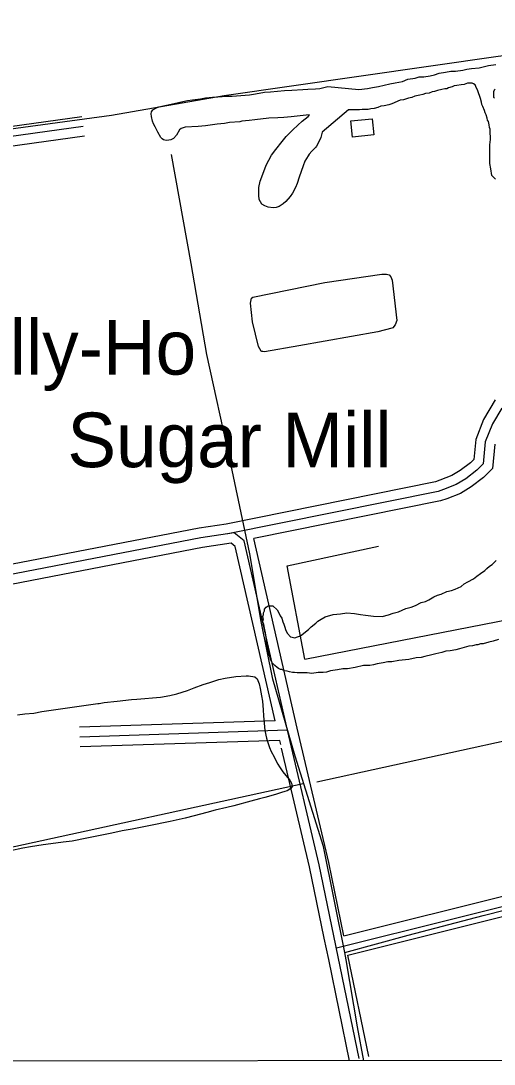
# Model space of a CAD drawing. Extents: x 3324104 to 3361979, y 612876 to 638273.
# Drawn here: x 3330722 to 3331443, y 618257 to 619844 of the extents above; entities that cross this region are included whole.
import ezdxf

# ---------------------------------------------------------------- set-up
doc = ezdxf.new("R2010")
doc.units = 0
for name, color, linetype in [('V-BLDG-IDEN', 7, 'Continuous'), ('V-BLDG-OTLN', 7, 'Continuous'), ('V-DTCH-CNTR', 7, 'Continuous'), ('V-GRID-FRAM', 7, 'Continuous'), ('V-ROAD-CNTR', 7, 'Continuous'), ('V-SITE-VEGE', 7, 'Continuous'), ('V-TOPO-SHOR', 7, 'Continuous')]:
    doc.layers.add(name, color=color, linetype=linetype)

msp = doc.modelspace()

# ---------------------------------------------------------------- linework, layer by layer
at = {"layer": 'V-BLDG-OTLN'}
msp.add_lwpolyline([(3331224.6, 619691.7), (3331257, 619695.1), (3331259.6, 619670.5), (3331227.2, 619667.1)], close=True, dxfattribs=at)
at = {"layer": 'V-DTCH-CNTR'}
for points in [[(3331244.5, 618262.2), (3331234.4, 618313.6), (3331217.5, 618415.7), (3331215.2, 618426.9), (3331182.8, 618587.9), (3331139.8, 618725.2), (3331105.6, 618842.5), (3331087.8, 618930.2), (3331070.9, 619033.1), (3331063.4, 619069.4), (3331040.2, 619177.1), (3331005.4, 619336.6), (3330981.6, 619474.6), (3330951.6, 619640.5)], [(3331215.2, 618426.9), (3331311.8, 618453.3), (3331425.9, 618482.8), (3331525.6, 618508.5), (3331632.5, 618535.7), (3331741.9, 618566), (3331832, 618591.7), (3331966.9, 618626.7), (3332061.8, 618649.2)]]:
    msp.add_lwpolyline(points, dxfattribs=at)
at = {"layer": 'V-GRID-FRAM'}
msp.add_lwpolyline([(3328194.1, 636440.7), (3359767.9, 636495.9), (3359807.6, 618312.1), (3328217.9, 618256.9), (3328194.1, 636440.7)], dxfattribs=at)
at = {"layer": 'V-ROAD-CNTR'}
for points in [[(3330007.1, 619586.3), (3330815, 619698.5)], [(3329995.1, 619569.5), (3330817.1, 619683.7)], [(3330012.9, 619556.8), (3330819.2, 619668.8)], [(3331444.2, 619267.6), (3331426.5, 619237.3), (3331414.5, 619206.9), (3331411.5, 619176.8), (3331406.4, 619171.7), (3331390.9, 619159.9), (3331378.2, 619152.2), (3331360.1, 619145), (3331353.2, 619142.6), (3331034.6, 619078.4)], [(3331454.2, 619254.8), (3331440, 619230.7), (3331429.2, 619203.4), (3331425.9, 619170), (3331416.3, 619160.4), (3331399.4, 619147.5), (3331384.9, 619138.7), (3331365.3, 619131), (3331357.2, 619128.1), (3331037.1, 619063.6)], [(3331443.9, 619199.8), (3331440.2, 619163.2), (3331426.2, 619149.1), (3331407.8, 619135.1), (3331391.6, 619125.2), (3331370.5, 619116.9), (3331361.2, 619113.6), (3331076.7, 619056.3)], [(3331034.6, 619078.4), (3330993.6, 619072.4), (3330135.7, 618906.7)], [(3331128.1, 618764.7), (3331062, 619053), (3331046.8, 619065), (3330996.1, 619057.6), (3330076.2, 618879.9), (3328787.7, 618630.3), (3328741.5, 618619.1), (3328711.6, 618607), (3328637.2, 618572.5)], [(3331109.4, 618779.1), (3331048.6, 619044.5), (3331042.6, 619049.2), (3330998.6, 619042.8), (3330140.4, 618877)], [(3331142.7, 618768), (3331076.7, 619056.3)], [(3331109.4, 618779.1), (3330811.3, 618769.4)], [(3331128.1, 618764.7), (3330811.8, 618754.5)], [(3331237.4, 618265.3), (3331176.3, 618560.3), (3331128.1, 618764.7)], [(3331214, 618452), (3331191, 618563.5), (3331142.7, 618768.1)], [(3331116.3, 618749.3), (3330812.3, 618739.5)], [(3331117.8, 618743.1), (3331116.3, 618749.3)], [(3331184.1, 618448.5), (3331161.7, 618557), (3331119, 618737.8)], [(3331202.5, 618433.7), (3331739.9, 618567.9), (3331755.7, 618571.8), (3331766.8, 618579.1), (3331772.9, 618588.7), (3331773.1, 618599.3), (3331778, 618664.4)], [(3331214, 618452), (3331736.2, 618582.4), (3331743.4, 618584.2)], [(3331220.1, 618422.6), (3331743.5, 618553.3), (3331753.8, 618555.9)], [(3331190.8, 618416.2), (3331184.1, 618448.5)], [(3331222.7, 618262.2), (3331190.8, 618416.2)], [(3331252.1, 618268.3), (3331220.1, 618422.6)]]:
    msp.add_lwpolyline(points, dxfattribs=at)
at = {"layer": 'V-SITE-VEGE'}
for points in [[(3331055.5, 619690.5), (3331039.7, 619689.1), (3331032.3, 619688), (3331021.3, 619686.7), (3331013.9, 619685.6), (3331003.4, 619684.3), (3330991.9, 619683.4), (3330972.1, 619682.1), (3330966.4, 619680.2), (3330963.5, 619678.3), (3330959.2, 619670), (3330954.7, 619665.2), (3330950.4, 619663.1), (3330944.2, 619662.1), (3330941.5, 619662.5), (3330939.3, 619663.1), (3330937.2, 619664.5), (3330935.5, 619666.6), (3330930.9, 619674.8), (3330928.4, 619679.5), (3330926.8, 619682.6), (3330924.2, 619687.3), (3330922.4, 619691.2), (3330920.9, 619698.6), (3330920.6, 619702.7), (3330921.2, 619705.4), (3330923.1, 619708.5), (3330927.8, 619711.2), (3330932.5, 619712.9), (3330944.1, 619715.7), (3330955.8, 619718.2), (3330964.4, 619720.3), (3330976, 619722.9), (3330983.6, 619724), (3330995.7, 619725.5), (3331003.3, 619726.6), (3331014.1, 619727.9), (3331022.1, 619728.4), (3331035.3, 619729.1), (3331043.9, 619729.5), (3331070.3, 619731.6), (3331079.2, 619732.9), (3331093, 619735.2), (3331102.2, 619735.9), (3331123.6, 619737.9), (3331134.6, 619738.4), (3331151.3, 619739.6), (3331159.3, 619740), (3331170.8, 619740.3), (3331177.4, 619740.8), (3331189.4, 619743.9), (3331236.9, 619739.6), (3331249.7, 619741.1), (3331257.7, 619742.7), (3331266.4, 619744.2), (3331284, 619748.1), (3331292, 619749.6), (3331303.1, 619751.9), (3331311.1, 619755.1), (3331322.3, 619756.6), (3331328.7, 619758.9), (3331335.8, 619758.9), (3331345.4, 619760.4), (3331351.8, 619762), (3331359, 619764.3), (3331368.5, 619765.8), (3331376.5, 619767.4), (3331383.7, 619767.3), (3331394.8, 619768.9), (3331401.2, 619770.4), (3331408.4, 619771.2), (3331419.6, 619772.7), (3331425.9, 619774.2), (3331433.9, 619775.8), (3331445.1, 619777.3)], [(3331436.5, 619679.4), (3331435.7, 619681.8), (3331434.9, 619685.8), (3331434.2, 619690.6), (3331432.6, 619693), (3331431.8, 619696.1), (3331430.3, 619700.9), (3331428.7, 619704.1), (3331427.9, 619707.3), (3331425.6, 619713.7), (3331424, 619716.9), (3331423.2, 619720.1), (3331421.6, 619725.7), (3331417.7, 619737.7), (3331414.6, 619744), (3331413.8, 619746.4), (3331411.4, 619748), (3331409.1, 619748.9), (3331401.9, 619748.9), (3331397.1, 619747.3), (3331392.3, 619746.6), (3331385.9, 619745.8), (3331381.9, 619745.1), (3331378.8, 619743.5), (3331373.2, 619741.9), (3331370.8, 619740.3), (3331367.6, 619740.4), (3331362.8, 619739.6), (3331356.4, 619738), (3331351.6, 619736.5), (3331348.4, 619735.7), (3331343.6, 619734.1), (3331338.1, 619733.4), (3331334.1, 619731.8), (3331329.3, 619731.1), (3331322.1, 619729.5), (3331317.3, 619727.1), (3331312.5, 619726.4), (3331304.5, 619724), (3331299.8, 619723.3), (3331287, 619717.8), (3331282.2, 619716.2), (3331275, 619714.7), (3331270.2, 619713.9), (3331265.4, 619712.3), (3331259.9, 619710.8), (3331255.1, 619710), (3331251.1, 619709.3), (3331241.5, 619709.3), (3331237.5, 619708.5), (3331220.8, 619708.7), (3331180.8, 619674.6), (3331180, 619670.5), (3331178.6, 619666.6), (3331174.7, 619657.7), (3331172.1, 619653.3), (3331170.8, 619651.3), (3331167.8, 619648.1), (3331165.3, 619645.7), (3331161.2, 619641.1), (3331159.4, 619638.8), (3331154.7, 619630.3), (3331151.9, 619623.5), (3331146, 619605.9), (3331143, 619596.4), (3331140.5, 619590.4), (3331135.9, 619581.8), (3331132.2, 619576.6), (3331125.8, 619569.3), (3331121.7, 619565.4), (3331115.6, 619561.6), (3331111.1, 619560.1), (3331106.5, 619559.7), (3331098.7, 619560.7), (3331093.7, 619562.3), (3331089, 619565), (3331085.2, 619572.3), (3331084.3, 619578.7), (3331084.7, 619590.3), (3331086.7, 619600), (3331092.1, 619614.8), (3331095.8, 619624.4), (3331103.9, 619639.5), (3331110.5, 619648.2), (3331119.8, 619660.6), (3331126.2, 619668.1), (3331136.2, 619678.2), (3331143.8, 619685.3), (3331150.6, 619691.1), (3331159.8, 619698.4), (3331161.6, 619701.1), (3331156.5, 619700.6), (3331147.2, 619699.3), (3331133.8, 619698), (3331122.5, 619697.1), (3331113.4, 619696.6), (3331099.6, 619696.1), (3331078.6, 619693.1), (3331069.7, 619692.4), (3331058.8, 619691.1), (3331055.5, 619690.5)], [(3331444, 619739.9), (3331442.4, 619738.3), (3331441.6, 619735.9), (3331441.6, 619727.9), (3331443.2, 619726.3)], [(3331444.8, 619602.9), (3331439.2, 619608.5), (3331437.7, 619618.8), (3331436.1, 619626.8), (3331436.3, 619655.5), (3331437.2, 619663.4), (3331437.2, 619667.4), (3331436.4, 619673), (3331436.5, 619679.4)], [(3331095.4, 618906.6), (3331094.6, 618912.9), (3331093.1, 618920.1), (3331092.3, 618925.7), (3331090.7, 618929.7), (3331091.6, 618933.7), (3331090.8, 618937.7), (3331091.6, 618940.8), (3331091.6, 618943.2), (3331093.2, 618946.4), (3331093.2, 618948.8), (3331095.7, 618952), (3331098.9, 618954.3), (3331106, 618954.3), (3331112.4, 618947.9), (3331115.5, 618942.3), (3331117.1, 618939.1), (3331119.4, 618935.1), (3331121, 618929.5), (3331122.6, 618926.3), (3331123.3, 618923.1), (3331125.7, 618916.7), (3331128.1, 618911.9), (3331132.8, 618907.1), (3331135.2, 618906.3), (3331139.2, 618905.5), (3331143.2, 618907.1), (3331147.9, 618908.6), (3331160, 618918.1), (3331164, 618922.1), (3331171.2, 618927.6), (3331174.4, 618930.8), (3331179.2, 618933.9), (3331185.6, 618937.1), (3331197.5, 618941), (3331208.7, 618941.7), (3331218.3, 618943.2), (3331230.2, 618942.3), (3331239, 618940.7), (3331246.9, 618939.8), (3331258.9, 618938.2), (3331272.4, 618938.1), (3331282, 618940.4), (3331289.1, 618942.8), (3331297.1, 618945.1), (3331308.3, 618949.8), (3331316.3, 618952.1), (3331322.7, 618954.5), (3331331.5, 618959.2), (3331337.9, 618960.8), (3331343.4, 618963.1), (3331350.6, 618967.8), (3331356.2, 618970.2), (3331361.8, 618971.8), (3331370.6, 618975.7), (3331377.8, 618977.2), (3331383.4, 618979.6), (3331392.2, 618983.5), (3331397, 618987.5), (3331402.6, 618990.6), (3331411.4, 618995.3), (3331416.2, 618999.3), (3331421.8, 619003.2), (3331428.2, 619008), (3331431.4, 619011.1), (3331435.4, 619014.3), (3331439.4, 619016.7), (3331445.8, 619023)], [(3331449, 618902.7), (3331441, 618900.4), (3331434.6, 618898.8), (3331425.9, 618896.5), (3331421.9, 618896.5), (3331417.9, 618894.9), (3331415.5, 618894.9), (3331409.9, 618893.4), (3331404.3, 618892.6), (3331390, 618888.7), (3331384.4, 618887.2), (3331375.6, 618885.6), (3331369.2, 618884.9), (3331362.8, 618883.3), (3331354.1, 618881), (3331347.7, 618879.5), (3331337.3, 618877.1), (3331331.7, 618875.6), (3331323.8, 618874.8), (3331312.6, 618872.5), (3331297.4, 618871), (3331287.1, 618868.7), (3331280.7, 618868.7), (3331273.5, 618867.2), (3331264.8, 618865.6), (3331259.2, 618864.1), (3331253.6, 618863.3), (3331244, 618863.4), (3331231.3, 618860.3), (3331219.3, 618858), (3331212.1, 618858), (3331204.2, 618856.5), (3331193.8, 618855), (3331187.4, 618853.4), (3331182.6, 618852.6), (3331174.7, 618852.7), (3331165.1, 618851.2), (3331157.9, 618852), (3331142.8, 618852.1), (3331138.8, 618852.9), (3331135.6, 618852.9), (3331130.9, 618853.8), (3331127.7, 618854.6), (3331123.7, 618855.4), (3331119.7, 618857), (3331117.3, 618857), (3331114.2, 618858.7), (3331112.6, 618860.3), (3331108.6, 618863.5), (3331104.7, 618867.5), (3331102.3, 618872.3), (3331101.5, 618875.5), (3331100, 618879.5), (3331098.4, 618886.6), (3331098.4, 618889.8), (3331096.9, 618897), (3331095.4, 618906.6)], [(3331082, 618843), (3331084.9, 618835.2), (3331086.6, 618828.4), (3331088.7, 618817.1), (3331090, 618809.1), (3331091.2, 618795.9), (3331091.8, 618786.6), (3331093.6, 618764.6), (3331096, 618752.8), (3331097, 618749.1), (3331100.6, 618738.8), (3331103.3, 618732.5), (3331107.7, 618724.5), (3331110, 618719.7), (3331113.6, 618713.2), (3331115.9, 618709), (3331120.9, 618701.5), (3331125.4, 618695.9), (3331131.7, 618688.8), (3331134.2, 618684.2), (3331135, 618679.5), (3331133.4, 618676.4), (3331127.6, 618672.9), (3331124, 618671.6), (3331118.8, 618670.1), (3331109.6, 618667.2), (3331093.7, 618662.7), (3331085.7, 618660.6), (3331072.3, 618656.8), (3331046.6, 618650), (3331035.7, 618647.3), (3331017.8, 618643.2), (3331005.4, 618639.9), (3330986.1, 618634.4), (3330972.1, 618631), (3330949.5, 618625.9), (3330916.9, 618619.5), (3330891.8, 618614.5), (3330876.4, 618611.6), (3330860.5, 618608.1), (3330837.9, 618603.5), (3330822.7, 618600.7), (3330800.6, 618596.2), (3330786.8, 618594.5), (3330767.7, 618592), (3330756.1, 618590.5), (3330737.2, 618587.3), (3330725.1, 618585.4), (3330706.5, 618581.5)], [(3330754.1, 618793.1), (3330839.2, 618805.5), (3330841.7, 618805.7), (3330849.3, 618806.8), (3330869, 618809.2), (3330890.9, 618811.4), (3330898.9, 618812.3), (3330934.6, 618815.2), (3330948.8, 618817.6), (3330959.5, 618820.3), (3330975.9, 618825.4), (3330986, 618829.4), (3331000, 618834.4), (3331009.8, 618837.6), (3331023.8, 618841.8), (3331033.1, 618844.1), (3331049.6, 618846.5), (3331065.4, 618847.8), (3331068.9, 618847.7), (3331078.2, 618845.9), (3331082, 618843)], [(3330717.1, 618788.4), (3330728.4, 618789.7), (3330742.2, 618791), (3330754.1, 618793.1)]]:
    msp.add_lwpolyline(points, dxfattribs=at)
at = {"layer": 'V-TOPO-SHOR'}
for p, q in [((3331172.6, 618686.4), (3331758.2, 618814.7)), ((3331151.9, 618683.4), (3330220.3, 618480.6))]:
    msp.add_line(p, q, dxfattribs=at)
for points in [[(3330023.1, 619586.8), (3330860.2, 619700.7), (3331031.7, 619730.5), (3331448.8, 619790.4), (3331842.2, 619841.4)], [(3331265.4, 619370.9), (3331145.5, 619349.4), (3331093, 619340.6), (3331090.7, 619341.1), (3331088.9, 619341.1), (3331088, 619341.5), (3331083.9, 619348.4), (3331074.6, 619386.3), (3331071.6, 619414.5), (3331073.5, 619422.3), (3331075.3, 619423.6), (3331184.8, 619445.7), (3331271.5, 619458.8), (3331278.8, 619458.8), (3331282.9, 619457.8), (3331285.6, 619454.6), (3331287.4, 619449.6), (3331294.7, 619388), (3331291.9, 619381.7), (3331288.3, 619377.1), (3331286.9, 619376.2), (3331265.4, 619370.9)], [(3331154.5, 618872.8), (3331843.6, 619007.1), (3331852.4, 619060.4), (3331911.5, 619087.1), (3332313.8, 619173.6)], [(3331154.5, 618872.8), (3331127.7, 619014.7), (3331266.7, 619044.6)]]:
    msp.add_lwpolyline(points, dxfattribs=at)

# ---------------------------------------------------------------- texts
at = {"layer": 'V-BLDG-IDEN'}
for s, p in [('Tally-Ho', (3330575.9, 619305.9)), ('Sugar Mill', (3330793.1, 619165))]:
    msp.add_text(s, height=83, rotation=359.9873, dxfattribs=at).set_placement(p)

doc.saveas('drawing.dxf')
